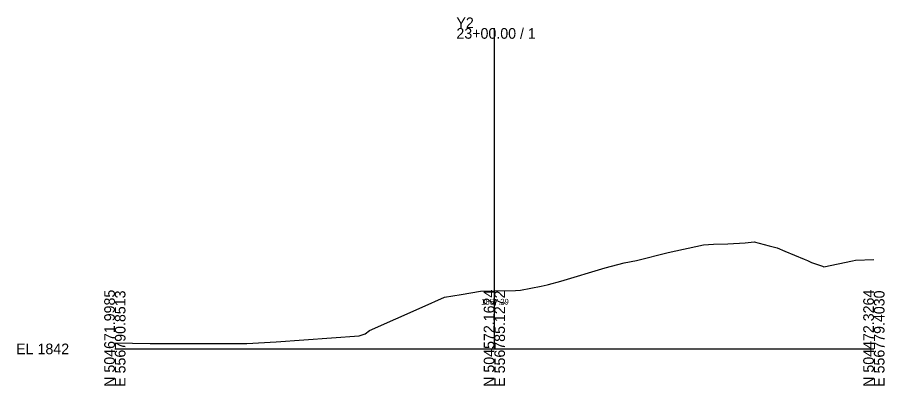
# Model space of a CAD drawing. Extents: x -26 to 1503, y -10 to 3574.
# Drawn here: x -25.7 to 202.8, y 2990.3 to 3087.4 of the extents above; entities that cross this region are included whole.
import ezdxf

# ---------------------------------------------------------------- set-up
doc = ezdxf.new("R2010")
doc.units = 0
for name, color, linetype in [('Default', 7, 'Continuous'), ('Exist Cross Section Cell', 7, 'Continuous'), ('Exist XS Center Line Elevation Label', 7, 'Continuous'), ('Exist XS Ground Line', 7, 'Continuous')]:
    doc.layers.add(name, color=color, linetype=linetype)

msp = doc.modelspace()

# ---------------------------------------------------------------- linework, layer by layer
at = {"layer": 'Exist Cross Section Cell'}
for p, q in [((100, 3000), (100, 3084.58)), ((0, 3000), (100, 3000)), ((100, 3000), (200, 3000))]:
    msp.add_line(p, q, dxfattribs=at)
at = {"layer": 'Exist XS Ground Line'}
for p, q in [((166.06, 3027.96), (168.48, 3028.19)), ((168.48, 3028.19), (172.42, 3027.2)), ((145.77, 3025.39), (155.14, 3027.46)), ((155.14, 3027.46), (157.72, 3027.62)), ((157.72, 3027.62), (161.56, 3027.74)), ((161.56, 3027.74), (166.06, 3027.96)), ((172.42, 3027.2), (174.55, 3026.66)), ((174.55, 3026.66), (176.53, 3025.81)), ((176.53, 3025.81), (181.61, 3023.65)), ((137.41, 3023.34), (145.77, 3025.39)), ((181.61, 3023.65), (182.48, 3023.34)), ((195.17, 3023.41), (200, 3023.6)), ((117.51, 3017.9), (129.16, 3021.35)), ((129.16, 3021.35), (134.17, 3022.65)), ((134.17, 3022.65), (137.41, 3023.34)), ((182.48, 3023.34), (183.56, 3022.82)), ((183.56, 3022.82), (186.44, 3021.77)), ((186.44, 3021.77), (186.82, 3021.65)), ((186.82, 3021.65), (194.33, 3023.22)), ((194.33, 3023.22), (195.17, 3023.41)), ((112.29, 3016.57), (113.9, 3016.88)), ((113.9, 3016.88), (114.23, 3016.97)), ((114.23, 3016.97), (117.51, 3017.9)), ((86.84, 3013.6), (91.23, 3014.36)), ((91.23, 3014.36), (96.31, 3015.19)), ((96.31, 3015.19), (100, 3015.29)), ((100, 3015.29), (105.57, 3015.42)), ((105.57, 3015.42), (106.93, 3015.5)), ((106.93, 3015.5), (112.29, 3016.57)), ((81.01, 3010.97), (86.84, 3013.6)), ((67.08, 3004.87), (81.01, 3010.97)), ((42.51, 3001.89), (64.36, 3003.42)), ((64.36, 3003.42), (65.95, 3003.97)), ((65.95, 3003.97), (67.08, 3004.87)), ((0, 3001.58), (9.32, 3001.42)), ((9.32, 3001.42), (24.77, 3001.45)), ((24.77, 3001.45), (34.79, 3001.46)), ((34.79, 3001.46), (42.51, 3001.89))]:
    msp.add_line(p, q, dxfattribs=at)

# ---------------------------------------------------------------- texts
at = {"layer": 'Default'}
msp.add_text('-', height=0.0001, dxfattribs=at).set_placement((0, 3000))
at = {"layer": 'Exist Cross Section Cell'}
for s, p in [('Y2', (90, 3084.58)), ('23+00.00 / 1', (90, 3081.78)), ('EL 1842', (-26, 2998.6))]:
    msp.add_text(s, height=2.8, dxfattribs=at).set_placement(p)
for s, p in [('N 504671.9985', (0, 2990)), ('E 556790.8513', (2.8, 2990)), ('N 504572.1624', (100, 2990)), ('E 556785.1272', (102.8, 2990)), ('N 504472.3264', (200, 2990)), ('E 556779.4030', (202.8, 2990))]:
    msp.add_text(s, height=2.8, rotation=90, dxfattribs=at).set_placement(p)
at = {"layer": 'Exist XS Center Line Elevation Label'}
msp.add_text('1857.29', height=1.5, dxfattribs=at).set_placement((96.54, 3011.69))

doc.saveas('drawing.dxf')
